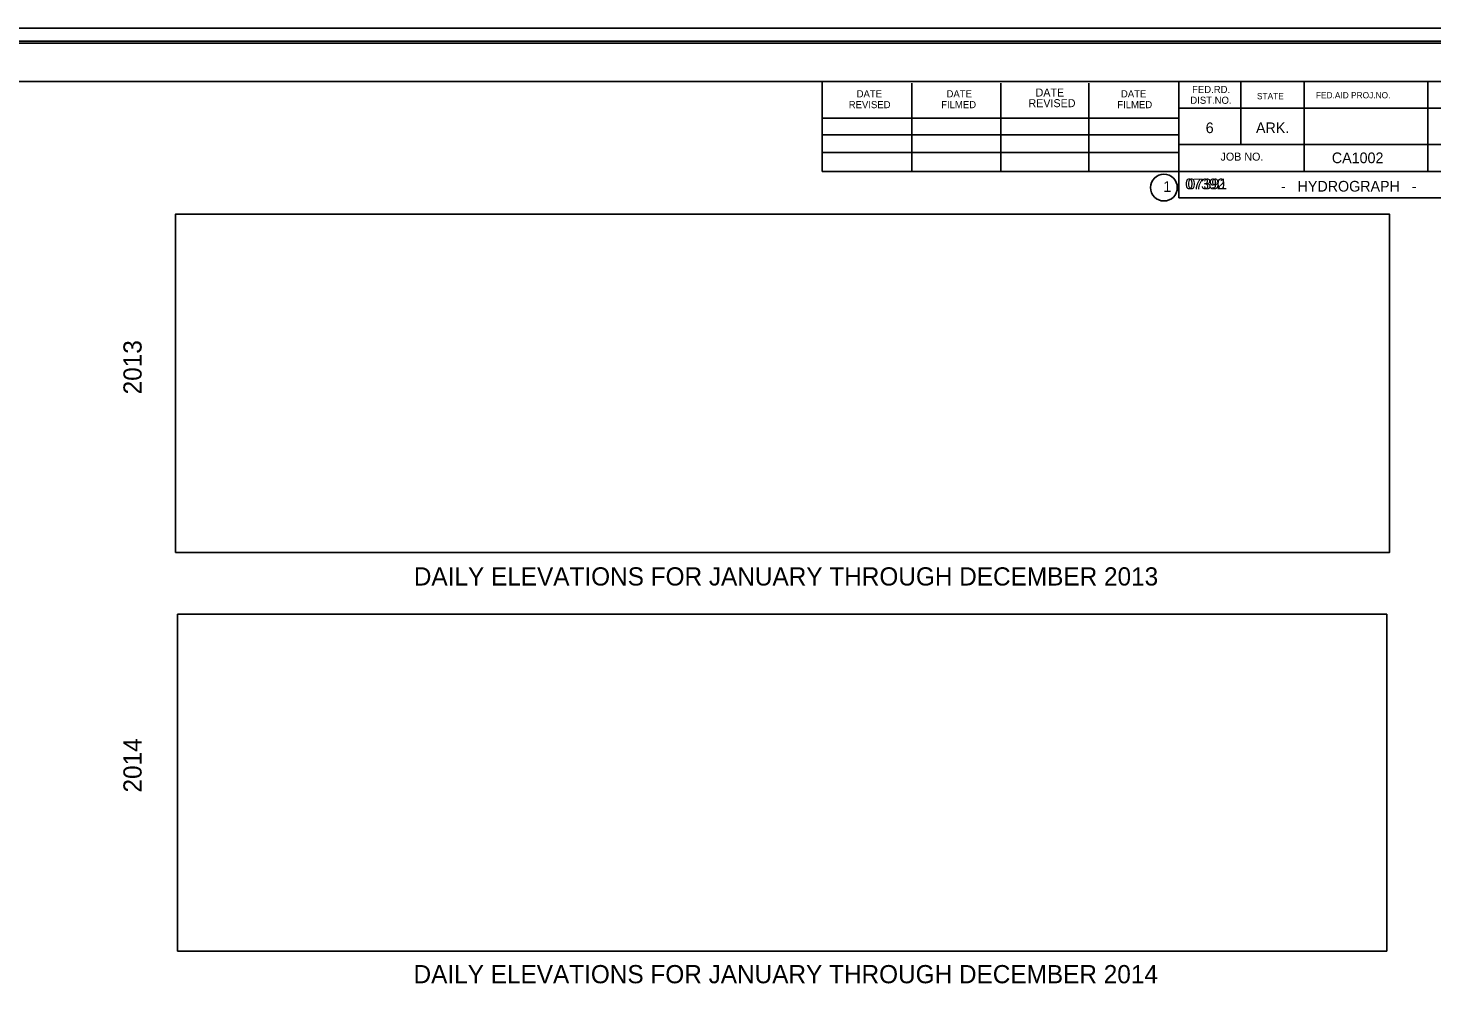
# Model space of a CAD drawing. Extents: x -1063117.9 to -1063075.9, y -253323.6 to -253301.6.
# Drawn here: x -1063101.09 to -1063085.67, y -253312.28 to -253301.63 of the extents above; entities that cross this region are included whole.
import ezdxf

# ---------------------------------------------------------------- set-up
doc = ezdxf.new("R2010")
doc.units = 0
for name, color, linetype in [('border', 7, 'Continuous'), ('Border 2660-Hwy18 - Level 62', 7, 'Continuous'), ('Border 2660-Hwy18 - Level 63', 7, 'Continuous'), ('Border 2660-Hwy18 - Text', 7, 'Continuous'), ('Bridge No BLFR', 7, 'Continuous'), ('Bridge No BLO', 7, 'Continuous'), ('Bridge No Ditch 81', 7, 'Continuous'), ('Dimensions', 7, 'Continuous'), ('Level 62 PDF', 7, 'Continuous'), ('Title Text', 7, 'Continuous')]:
    doc.layers.add(name, color=color, linetype=linetype)

msp = doc.modelspace()

# ---------------------------------------------------------------- linework, layer by layer
at = {"layer": 'border'}
for p, q in [((-1063116.157, -253302.216), (-1063084.146, -253302.216)), ((-1063092.372, -253303.204), (-1063092.372, -253302.216)), ((-1063091.387, -253303.204), (-1063091.387, -253302.235)), ((-1063090.41, -253303.204), (-1063090.41, -253302.235)), ((-1063089.443, -253303.204), (-1063089.443, -253302.235)), ((-1063088.456, -253302.216), (-1063088.456, -253303.495)), ((-1063087.772, -253302.216), (-1063087.772, -253302.91)), ((-1063087.078, -253302.216), (-1063087.078, -253303.204)), ((-1063085.72, -253302.216), (-1063085.72, -253303.204)), ((-1063084.146, -253302.51), (-1063088.456, -253302.51)), ((-1063092.372, -253302.618), (-1063088.456, -253302.618)), ((-1063092.372, -253302.804), (-1063088.456, -253302.804)), ((-1063092.372, -253303.204), (-1063092.372, -253302.997)), ((-1063092.372, -253302.997), (-1063088.456, -253302.997)), ((-1063084.146, -253302.91), (-1063088.456, -253302.91)), ((-1063088.16, -253302.91), (-1063084.146, -253302.91)), ((-1063084.146, -253303.204), (-1063092.372, -253303.204)), ((-1063088.456, -253303.495), (-1063084.146, -253303.495))]:
    msp.add_line(p, q, dxfattribs=at)
msp.add_circle((-1063088.618, -253303.382), 0.147, dxfattribs=at)
at = {"layer": 'Border 2660-Hwy18 - Level 62'}
msp.add_lwpolyline([(-1063117.777, -253301.63), (-1063083.659, -253301.63), (-1063083.659, -253323.44), (-1063117.777, -253323.44)], close=True, dxfattribs=at)
at = {"layer": 'Border 2660-Hwy18 - Level 63'}
msp.add_lwpolyline([(-1063117.888, -253301.773), (-1063083.889, -253301.773), (-1063083.889, -253323.143), (-1063117.888, -253323.143)], close=True, dxfattribs=at)
at = {"layer": 'Dimensions'}
for points in [[(-1063099.473, -253307.389), (-1063086.14, -253307.389), (-1063086.14, -253303.674), (-1063099.473, -253303.674)], [(-1063099.449, -253311.767), (-1063086.171, -253311.767), (-1063086.171, -253308.068), (-1063099.449, -253308.068)]]:
    msp.add_lwpolyline(points, close=True, dxfattribs=at)
at = {"layer": 'Level 62 PDF'}
msp.add_lwpolyline([(-1063117.527, -253301.797), (-1063083.409, -253301.797), (-1063083.409, -253323.607), (-1063117.527, -253323.607)], close=True, dxfattribs=at)

# ---------------------------------------------------------------- texts
at = {"layer": 'Border 2660-Hwy18 - Text'}
for s, height, p in [('FED.RD.', 0.0782, (-1063088.309, -253302.343)), ('DATE', 0.0782, (-1063091.992, -253302.391)), ('DATE', 0.0782, (-1063091.005, -253302.391)), ('REVISED', 0.0879, (-1063090.105, -253302.499)), ('DATE', 0.0879, (-1063090.027, -253302.382)), ('DATE', 0.0782, (-1063089.09, -253302.391)), ('DIST.NO.', 0.0782, (-1063088.328, -253302.462)), ('STATE', 0.0684, (-1063087.596, -253302.412)), ('FED.AID PROJ.NO.', 0.06839, (-1063086.949, -253302.402)), ('REVISED', 0.0782, (-1063092.079, -253302.51)), ('FILMED', 0.0782, (-1063091.064, -253302.51)), ('FILMED', 0.0782, (-1063089.13, -253302.51)), ('6', 0.117, (-1063088.159, -253302.784)), ('ARK.', 0.1172, (-1063087.607, -253302.784)), ('JOB NO.', 0.0879, (-1063087.996, -253303.086)), ('CA1002', 0.1172, (-1063086.774, -253303.114)), ('1', 0.117, (-1063088.625, -253303.429))]:
    msp.add_text(s, height=height, dxfattribs=at).set_placement(p)
at = {"layer": 'Bridge No BLFR'}
msp.add_text('07392', height=0.1172, dxfattribs=at).set_placement((-1063088.385, -253303.4))
at = {"layer": 'Bridge No BLO'}
msp.add_text('07391', height=0.1172, dxfattribs=at).set_placement((-1063088.359, -253303.4))
at = {"layer": 'Bridge No Ditch 81'}
msp.add_text('07390', height=0.1172, dxfattribs=at).set_placement((-1063088.384, -253303.4))
at = {"layer": 'Title Text'}
for s, height, p in [('-   HYDROGRAPH   -', 0.11722, (-1063087.333, -253303.426)), (' DAILY ELEVATIONS FOR JANUARY THROUGH DECEMBER 2013 ', 0.2, (-1063096.929, -253307.752)), (' DAILY ELEVATIONS FOR JANUARY THROUGH DECEMBER 2014 ', 0.2, (-1063096.932, -253312.12))]:
    msp.add_text(s, height=height, dxfattribs=at).set_placement(p)
for s, p in [('2013', (-1063099.844, -253305.653)), ('2014', (-1063099.844, -253310.025))]:
    msp.add_text(s, height=0.2, rotation=90, dxfattribs=at).set_placement(p)

doc.saveas('drawing.dxf')
